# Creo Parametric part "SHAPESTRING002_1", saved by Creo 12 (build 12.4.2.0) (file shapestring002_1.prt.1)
Units: Custom; MM, KILOGRAM, SECS

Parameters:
  PTC_WM_ITERATION = "0"
  PTC_WM_VERSION = "-.0"
  PTC_WM_LIFECYCLE_STATE = "In Work"
  PTC_WM_LIFECYCLE = "MO_CADDocument"
  PTC_WM_CREATED_BY = "Maximilian Roepper (Z0017RMS: MO)"
  PTC_WM_CREATED_ON = "18-Sep-26 11:36:42 AM"
  PTC_WM_MODIFIED_BY = "Maximilian Roepper (Z0017RMS: MO)"
  PTC_WM_MODIFIED_ON = "18-Sep-26 11:36:46 AM"
  PDMLINKNUMBER = "PDM000071455116"
  PTC_WM_NAME = "shapestring002_1.prt"
  PTC_WM_NUMBER = "PDM000071455116"

Other parameters: WEIGHT, WEIGHT_FACTOR, WEIGHT_ADD, _MASS_TEMP, _DIFF_TEMP, MC_ERRORS, SUPPLIER

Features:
  1. coordinate system
  2. datum plane "PRT_YZ"
  3. datum plane "PRT_XY"
  4. datum plane "PRT_XZ"
  5. coordinate system
  6. datum axis
  7. datum axis
  8. datum axis
  9. coordinate system
  10. imported feature
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
Other named items: PRT, SIEMENS_MO, DRW_VIEW_ORG, PRT_X, PRT_Y, PRT_Z, CS0, ROUGH_GROB

Layers: 00_STD_CSYS-KSYS, 01_STD_PLANES-EBENEN, 02_STD_AXES-ACHSEN, 03_STD_CSYS-KSYS, 24_IMPORT_FEAT-IMPORT_KE, WHITE

Surfaces: 1 plane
